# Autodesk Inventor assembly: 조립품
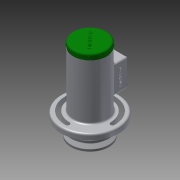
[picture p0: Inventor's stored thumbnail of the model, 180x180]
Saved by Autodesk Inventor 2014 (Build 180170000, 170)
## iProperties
Created: 2017-05
Part Number: 조립품
Document SubType Name: Assembly
Designer: Administrator
Author: Administrator
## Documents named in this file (20)
- C:\Users\Administrator\Desktop\470507V1009\470507V1009 (2)\조립품.iam
- C:\Users\Administrator\Desktop\470507V1009\470507V1009 (2)\V-벨트풀리.ipt
- C:\Users\Administrator\Desktop\470507V1009\470507V1009 (2)\너트 M10.ipt
- C:\Users\Administrator\Desktop\470507V1009\470507V1009 (2)\멈춤링 15 x 1.ipt
- C:\Users\Administrator\Desktop\470507V1009\470507V1009 (2)\멈춤링 35x1.6.ipt
- C:\Users\Administrator\Desktop\470507V1009\470507V1009 (2)\베어링 15 x 35 x 11.ipt
- C:\Users\Administrator\Desktop\470507V1009\470507V1009 (2)\본체.ipt
- C:\Users\Administrator\Desktop\470507V1009\470507V1009 (2)\볼트 M4 x 10.ipt
- C:\Users\Administrator\Desktop\470507V1009\470507V1009 (2)\부시1.ipt
- C:\Users\Administrator\Desktop\470507V1009\470507V1009 (2)\부시2.ipt
- C:\Users\Administrator\Desktop\470507V1009\470507V1009 (2)\사이드 커버.ipt
- 사이드 커버.ipt
- C:\Users\Administrator\Desktop\470507V1009\470507V1009 (2)\십자볼트 M3 x 10.ipt
- C:\Users\Administrator\Desktop\470507V1009\470507V1009 (2)\오일 실 15 25 7.ipt
- C:\Users\Administrator\Desktop\470507V1009\470507V1009 (2)\와셔 3x6.ipt
- C:\Users\Administrator\Desktop\470507V1009\470507V1009 (2)\와셔 4x16.ipt
- C:\Users\Administrator\Desktop\470507V1009\470507V1009 (2)\와셔 10x21.ipt
- C:\Users\Administrator\Desktop\470507V1009\470507V1009 (2)\축.ipt
- C:\Users\Administrator\Desktop\470507V1009\470507V1009 (2)\키 4 x 4 x 18.ipt
- C:\Users\Administrator\Desktop\470507V1009\470507V1009 (2)\탑 커버.ipt
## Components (2 placed, 2 different names)
1. V-벨트풀리:1 — 각도:2
2. ISO 4017 M4 x 10:1 — 각도:1, 각도:2
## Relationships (2: Angle 2)
- 각도:1 [Angle]: ISO 4017 M4 x 10:1
- 각도:2 [Angle]: V-벨트풀리:1 ↔ ISO 4017 M4 x 10:1
